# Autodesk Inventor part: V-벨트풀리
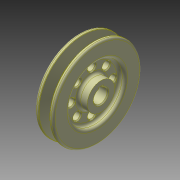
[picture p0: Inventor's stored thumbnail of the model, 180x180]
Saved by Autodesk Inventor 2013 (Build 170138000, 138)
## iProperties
Created: 2011-02
Part Number: V-벨트풀리
Document SubType Name: Modeling
Designer: pww
Density: 1 g/cm^3
Material: 알루미늄 6061
Author: pww
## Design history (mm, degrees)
sketch "스케치1"
  geometry: L1 (0, 0)-(24, 0); L2 (0, 7.5)-(24, 7.5); L3 (24, 7.5)-(24, 15); L4 (24, 15)-(14, 15); L5 (14, 15)-(14, 30); L6 (14, 30)-(20, 30); L7 (20, 30)-(20, 48); L8 (20, 48)-(15.976, 48); L9 (15.976, 48)-(12.154, 35.5); L10 (12.154, 35.5)-(7.846, 35.5); L11 (7.846, 35.5)-(4.024, 48); L12 (4.024, 48)-(0, 48); L13 (0, 48)-(0, 30); L14 (0, 30)-(6, 30); L15 (6, 30)-(6, 15); L16 (6, 15)-(0, 15); L17 (0, 15)-(0, 7.5); 2 further points
  constraints: 34 end point, 13 parallel, 4 equal length, 3 collinear, 2 point on line, 2 vertical alignment, 1 horizontal, 1 horizontal alignment, 1 perpendicular
  dimensions: "d0" = 24 distance of L1.start L1.end; "d1" = 34 deg angle of L9 L11; "d2" = 9.2 distance of point (14.6, 43.5) point (5.4, 43.5); "d3" = 4.5 distance from line of point (5.4, 43.5) L12; "d4" = 8 distance from line of L10 point (5.4, 43.5); "d5" = 8 distance between parallel lines of L5 L15; "d6" = 6 distance of L13.end L14.end; "d7" = 15 diameter of L2 L1; "d8" = 30 diameter of L4 L1; "d9" = 60 diameter of L6 L1; "d10" = 96 diameter of L8 L1
revolve "회전1" sketch "스케치1" stored, may be unused: angle "d11" = 90 deg
fillet "모깎기1" dims "d12" = 2, "d13" = 1, "d14" = 0.5, "d15" = 3
sketch "스케치2"
  geometry: L1 (-2.5, 7.071)-(2.5, 7.071); L2 (2.5, 7.071)-(2.5, 9.8); L3 (2.5, 9.8)-(-2.5, 9.8); L4 (-2.5, 9.8)-(-2.5, 7.071); A1 r 7.5 centre (0, 0) between (-2.5, 7.071) and (2.5, 7.071) reference; 1 further point
  constraints: 8 end point, 2 parallel, 2 point on circle, 1 horizontal, 1 perpendicular
  dimensions: "d16" = 17.3 dimension on A1 L3; "d17" = 5 distance of L2.end L3.end
extrude "돌출1" cut sketch "스케치2" stored distance "d18" = 10; taper "d19" = 0 deg
sketch "스케치3"
  geometry: 4 further points
  constraints: 2 horizontal alignment, 1 vertical alignment, 1 other
  dimensions: "d20" = 22.5 distance of point (0, 22.5) point (0, 0)
hole "구멍1" sketch "스케치3" at (0, 22.5) diameter "d22" = 8; stored, may be unused: countersink angle "d26" = 90 deg, drill point angle "d28" = 118 deg; dims "d23" = 6, "d24" = 4, "d25" = 2, "d27" = 8
chamfer "모따기1" distance "d33" = 1; stored, may be unused: second distance "d34" = 2, angle "d35" = 45 deg
node "솔리드1"
pattern_circular "원형 패턴1" dims angle "d31" = 360 deg
